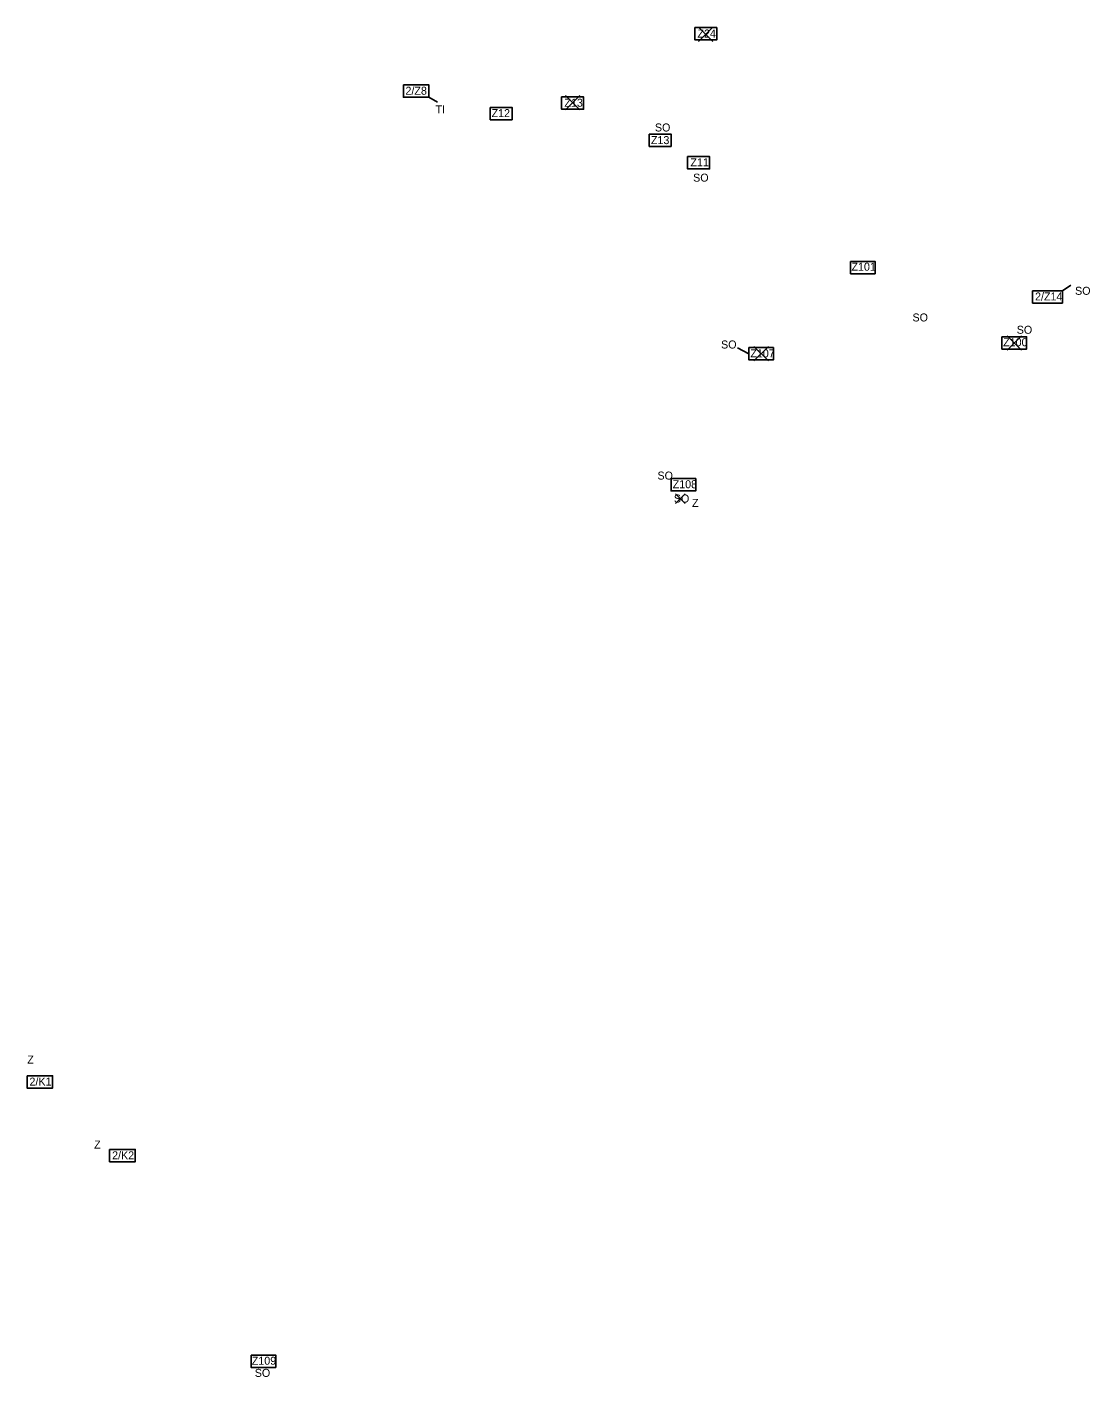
# Model space of a CAD drawing. Extents: x -443466 to -436070, y -1146578 to -1129775.
# Drawn here: x -443466 to -442137, y -1133457 to -1131770 of the extents above; entities that cross this region are included whole.
import ezdxf

# ---------------------------------------------------------------- set-up
doc = ezdxf.new("R2010")
doc.units = 0
for name, color, linetype in [('Vrstva 3', 7, 'Continuous'), ('Vrstva 4', 7, 'Continuous'), ('Vrstva 50', 7, 'Continuous'), ('Vrstva 85', 7, 'Continuous')]:
    doc.layers.add(name, color=color, linetype=linetype)

msp = doc.modelspace()

# ---------------------------------------------------------------- linework, layer by layer
at = {"layer": 'Vrstva 3'}
for p, q in [((-442963.8, -1131857.8), (-442953.2, -1131864)), ((-442171.9, -1132099.6), (-442161.5, -1132092.6)), ((-442563.8, -1132178.3), (-442578.2, -1132171.1))]:
    msp.add_line(p, q, dxfattribs=at)
for points in [[(-442631.4, -1131770.7), (-442604, -1131770.7), (-442604, -1131786.1), (-442631.4, -1131786.1)], [(-442995.6, -1131842.4), (-442963.8, -1131842.4), (-442963.8, -1131857.8), (-442995.6, -1131857.8)], [(-442887.2, -1131870.5), (-442859.8, -1131870.5), (-442859.8, -1131885.9), (-442887.2, -1131885.9)], [(-442797.9, -1131857.5), (-442770.5, -1131857.5), (-442770.5, -1131872.9), (-442797.9, -1131872.9)], [(-442688.4, -1131903.9), (-442661.1, -1131903.9), (-442661.1, -1131919.3), (-442688.4, -1131919.3)], [(-442640.4, -1131931.9), (-442613, -1131931.9), (-442613, -1131947.3), (-442640.4, -1131947.3)], [(-442640.4, -1131931.9), (-442613, -1131931.9), (-442613, -1131947.3), (-442640.4, -1131947.3)], [(-442640.4, -1131931.9), (-442613, -1131931.9), (-442613, -1131947.3), (-442640.4, -1131947.3)], [(-442436.8, -1132062.9), (-442406.1, -1132062.9), (-442406.1, -1132078.3), (-442436.8, -1132078.3)], [(-442209.2, -1132099.6), (-442171.9, -1132099.6), (-442171.9, -1132115), (-442209.2, -1132115)], [(-442247.5, -1132157.2), (-442216.7, -1132157.2), (-442216.7, -1132172.6), (-442247.5, -1132172.6)], [(-442563.8, -1132170.6), (-442533.1, -1132170.6), (-442533.1, -1132186), (-442563.8, -1132186)], [(-442661, -1132334.4), (-442630.2, -1132334.4), (-442630.2, -1132349.8), (-442661, -1132349.8)], [(-443466.2, -1133080.6), (-443434.2, -1133080.6), (-443434.2, -1133096), (-443466.2, -1133096)], [(-443363, -1133172.7), (-443330.8, -1133172.7), (-443330.8, -1133188.1), (-443363, -1133188.1)], [(-443186, -1133429.7), (-443155.2, -1133429.7), (-443155.2, -1133445.1), (-443186, -1133445.1)]]:
    msp.add_lwpolyline(points, close=True, dxfattribs=at)
at = {"layer": 'Vrstva 50'}
for p, q in [((-442655.5, -1132365.3), (-442643.5, -1132353.3)), ((-442655.5, -1132353.3), (-442643.5, -1132365.3))]:
    msp.add_line(p, q, dxfattribs=at)
at = {"layer": 'Vrstva 85'}
for p, q in [((-442626.9, -1131770.1), (-442608.9, -1131788.1)), ((-442608.9, -1131770.1), (-442626.9, -1131788.1)), ((-442793, -1131855.7), (-442775, -1131873.7)), ((-442775, -1131855.7), (-442793, -1131873.7)), ((-442241.1, -1132155.9), (-442223.1, -1132173.9)), ((-442223.1, -1132155.9), (-442241.1, -1132173.9)), ((-442241.1, -1132155.9), (-442223.1, -1132173.9)), ((-442223.1, -1132155.9), (-442241.1, -1132173.9)), ((-442557.5, -1132169.3), (-442539.5, -1132187.3)), ((-442539.5, -1132169.3), (-442557.5, -1132187.3))]:
    msp.add_line(p, q, dxfattribs=at)

# ---------------------------------------------------------------- texts
at = {"layer": 'Vrstva 3'}
for s, p in [('Z24', (-442628.1, -1131783.2)), ('2/Z8', (-442993.1, -1131854.7)), ('Z13', (-442794.4, -1131869.7)), ('Z12', (-442885.5, -1131882.7)), ('Z13', (-442686.3, -1131916.4)), ('Z11', (-442636.9, -1131944.2)), ('Z11', (-442636.9, -1131944.2)), ('Z11', (-442636.9, -1131944.2)), ('Z101', (-442435.6, -1132074.6)), ('2/Z14', (-442206.1, -1132111.8)), ('Z100', (-442246, -1132169)), ('Z107', (-442562, -1132182.9)), ('Z108', (-442659.1, -1132346.4)), ('2/K1', (-443463.1, -1133092.9)), ('2/K2', (-443359.8, -1133185)), ('Z109', (-443185.2, -1133441.7))]:
    msp.add_text(s, height=10, dxfattribs=at).set_placement(p)
at = {"layer": 'Vrstva 4'}
for s, p in [('TI', (-442955.5, -1131878)), ('SO', (-442681.3, -1131900.6)), ('SO', (-442633.5, -1131963.3)), ('SO', (-442633.5, -1131963.3)), ('SO', (-442633.5, -1131963.3)), ('SO', (-442156.1, -1132104.7)), ('SO', (-442359.3, -1132138)), ('SO', (-442359.3, -1132138)), ('SO', (-442229, -1132153.4)), ('SO', (-442598.6, -1132171.8)), ('SO', (-442678.1, -1132335.6)), ('SO', (-442657.6, -1132364.3)), ('Z', (-442634.9, -1132369.7)), ('Z', (-443465.9, -1133065.4)), ('Z', (-443382.3, -1133171.6)), ('SO', (-443181.5, -1133456.9))]:
    msp.add_text(s, height=10, dxfattribs=at).set_placement(p)

doc.saveas('drawing.dxf')
